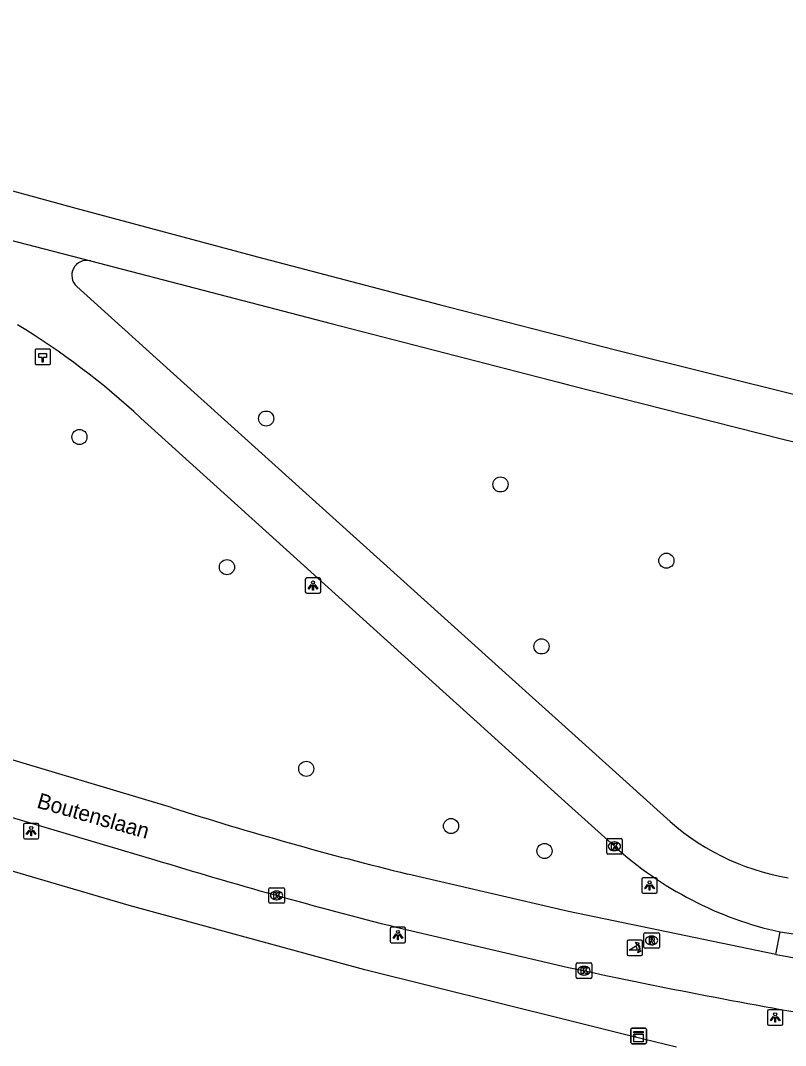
# Model space of a CAD drawing. Extents: x 160203 to 161526, y 379529 to 381797.
# Drawn here: x 160964.6 to 161014, y 381727.7 to 381793.9 of the extents above; entities that cross this region are included whole.
import ezdxf

# ---------------------------------------------------------------- set-up
doc = ezdxf.new("R2010")
doc.units = 0
for name, color, linetype in [('IMGEO_Boom', 7, 'Continuous'), ('IMGEO_Fietspad_gesloten', 7, 'Continuous'), ('IMGEO_Hectometerpaal', 7, 'Continuous'), ('IMGEO_Kast', 7, 'Continuous'), ('IMGEO_Kolk', 7, 'Continuous'), ('IMGEO_Lichtpunt', 7, 'Continuous'), ('IMGEO_Openbare_ruimte_label', 7, 'Continuous'), ('IMGEO_Poller', 7, 'Continuous'), ('IMGEO_Rijbaan_lokaal_gesloten', 7, 'Continuous'), ('IMGEO_Rijbaan_regionaal_gesloten', 7, 'Continuous'), ('IMGEO_Rioolput', 7, 'Continuous'), ('IMGEO_Verkeerseiland_open', 7, 'Continuous'), ('IMGEO_Voetpad_open', 7, 'Continuous')]:
    doc.layers.add(name, color=color, linetype=linetype)

msp = doc.modelspace()

# ---------------------------------------------------------------- linework, layer by layer
at = {"layer": 'IMGEO_Boom'}
for centre in [(160980.462, 381768.218), (160968.397, 381767.028), (160995.597, 381763.962), (161006.319, 381759.033), (160977.927, 381758.616), (160998.247, 381753.494), (160983.05, 381745.584), (160992.404, 381741.885), (160998.446, 381740.273)]:
    msp.add_circle(centre, 0.489, dxfattribs=at)
at = {"layer": 'IMGEO_Fietspad_gesloten'}
for points in [[(160974.354, 381743.083), (160951.205, 381750), (160921.356, 381758.919)], [(160913.952, 381757.333), (160917.435, 381756.293), (160921.939, 381754.948), (160938.727, 381750), (160941.676, 381749.131), (160960.405, 381743.51), (160973.259, 381739.709)], [(161013.385, 381733.585), (161000, 381736.362), (160989.623, 381738.784)], [(160988.869, 381735.348), (161000, 381732.75)]]:
    msp.add_lwpolyline(points, dxfattribs=at)
for centre, radius, start, end in [((161042.483, 381955.797), 223.358, 252.24042, 256.31036), ((161066.527, 382043.438), 317.727, 252.92958, 255.85265), ((161067.918, 382023.698), 295.194, 259.35423, 261.73648), ((161079.415, 382097.832), 373.62, 257.72776, 260.3637)]:
    msp.add_arc(centre, radius, start, end, dxfattribs=at)
at = {"layer": 'IMGEO_Hectometerpaal'}
for p, q in [((160966.449, 381772.71), (160965.608, 381772.71)), ((160966.449, 381772.71), (160965.608, 381772.71)), ((160966.533, 381771.794), (160966.533, 381772.635)), ((160966.533, 381771.794), (160966.533, 381772.635)), ((160965.533, 381772.626), (160965.533, 381771.785)), ((160965.533, 381772.626), (160965.533, 381771.785)), ((160965.617, 381771.71), (160966.458, 381771.71)), ((160965.617, 381771.71), (160966.458, 381771.71))]:
    msp.add_line(p, q, dxfattribs=at)
msp.add_lwpolyline([(160966.058, 381771.854), (160965.998, 381771.854), (160965.998, 381772.159), (160965.778, 381772.159), (160965.778, 381772.428), (160966.278, 381772.428), (160966.278, 381772.159), (160966.058, 381772.159), (160966.058, 381771.854)], dxfattribs=at)
for centre, start, end in [((160965.611, 381772.632), 92.4484, 184.28452), ((160965.611, 381772.632), 92.4484, 184.28452), ((160966.455, 381772.632), 2.4484, 94.28452), ((160966.455, 381772.632), 2.4484, 94.28452), ((160965.611, 381771.788), 182.4484, 274.28452), ((160965.611, 381771.788), 182.4484, 274.28452), ((160966.455, 381771.788), 272.4484, 4.28452), ((160966.455, 381771.788), 272.4484, 4.28452)]:
    msp.add_arc(centre, 0.0779, start, end, dxfattribs=at)
at = {"layer": 'IMGEO_Kast'}
for p, q in [((161004.026, 381727.893), (161004.026, 381728.734)), ((161004.026, 381728.734), (161004.026, 381727.893)), ((161004.101, 381728.818), (161004.942, 381728.818)), ((161004.942, 381728.818), (161004.101, 381728.818)), ((161005.026, 381728.743), (161005.026, 381727.902)), ((161005.026, 381727.902), (161005.026, 381728.743)), ((161004.951, 381727.818), (161004.11, 381727.818)), ((161004.11, 381727.818), (161004.951, 381727.818))]:
    msp.add_line(p, q, dxfattribs=at)
for points in [[(161004.221, 381728.608), (161004.821, 381728.608), (161004.821, 381728.523), (161004.221, 381728.523), (161004.221, 381728.608)], [(161004.221, 381728.433), (161004.821, 381728.433), (161004.821, 381727.944), (161004.221, 381727.944), (161004.221, 381728.433)]]:
    msp.add_lwpolyline(points, dxfattribs=at)
msp.add_circle((161004.305, 381728.282), 0.0377, dxfattribs=at)
for centre, start, end in [((161004.104, 381728.74), 92.4484, 184.28452), ((161004.104, 381728.74), 92.4484, 184.28452), ((161004.948, 381728.74), 2.4484, 94.28452), ((161004.948, 381728.74), 2.4484, 94.28452), ((161004.104, 381727.896), 182.4484, 274.28452), ((161004.104, 381727.896), 182.4484, 274.28452), ((161004.948, 381727.896), 272.4484, 4.28452), ((161004.948, 381727.896), 272.4484, 4.28452)]:
    msp.add_arc(centre, 0.0779, start, end, dxfattribs=at)
at = {"layer": 'IMGEO_Kolk'}
for p, q in [((161002.461, 381740.151), (161002.461, 381741.003)), ((161002.536, 381741.077), (161003.388, 381741.077)), ((161002.949, 381740.857), (161002.974, 381740.857)), ((161003.462, 381741.003), (161003.462, 381740.151)), ((161002.972, 381740.297), (161002.947, 381740.297)), ((161003.388, 381740.077), (161002.536, 381740.077)), ((160980.635, 381736.974), (160980.635, 381737.826)), ((160980.71, 381737.9), (160981.562, 381737.9)), ((160981.123, 381737.68), (160981.148, 381737.68)), ((160981.636, 381737.826), (160981.636, 381736.974)), ((160981.562, 381736.9), (160980.71, 381736.9)), ((160981.146, 381737.12), (160981.121, 381737.12)), ((161000.493, 381732.108), (161000.493, 381732.96)), ((161000.568, 381733.034), (161001.42, 381733.034)), ((161001.494, 381732.96), (161001.494, 381732.108)), ((161001.004, 381732.254), (161000.979, 381732.254)), ((161000.981, 381732.814), (161001.006, 381732.814)), ((161001.42, 381732.034), (161000.568, 381732.034))]:
    msp.add_line(p, q, dxfattribs=at)
for points in [[(161002.461, 381740.151), (161002.461, 381741.003)], [(161002.536, 381741.077), (161003.388, 381741.077)], [(161003.462, 381741.003), (161003.462, 381740.151)], [(161002.782, 381740.777), (161002.905, 381740.777), (161002.905, 381740.626), (161003.035, 381740.777), (161003.199, 381740.777), (161003.053, 381740.626), (161003.206, 381740.377), (161003.054, 381740.377), (161002.969, 381740.541), (161002.905, 381740.474), (161002.905, 381740.377), (161002.782, 381740.377), (161002.782, 381740.777)], [(161003.388, 381740.077), (161002.536, 381740.077)], [(160980.635, 381736.974), (160980.635, 381737.826)], [(160980.71, 381737.9), (160981.562, 381737.9)], [(160980.956, 381737.6), (160981.079, 381737.6), (160981.079, 381737.449), (160981.209, 381737.6), (160981.373, 381737.6), (160981.227, 381737.449), (160981.38, 381737.2), (160981.228, 381737.2), (160981.143, 381737.364), (160981.079, 381737.297), (160981.079, 381737.2), (160980.956, 381737.2), (160980.956, 381737.6)], [(160981.636, 381737.826), (160981.636, 381736.974)], [(160981.562, 381736.9), (160980.71, 381736.9)], [(161000.493, 381732.108), (161000.493, 381732.96)], [(161000.568, 381733.034), (161001.42, 381733.034)], [(161001.494, 381732.96), (161001.494, 381732.108)], [(161000.814, 381732.734), (161000.937, 381732.734), (161000.937, 381732.583), (161001.067, 381732.734), (161001.231, 381732.734), (161001.085, 381732.583), (161001.238, 381732.334), (161001.086, 381732.334), (161001.001, 381732.498), (161000.937, 381732.431), (161000.937, 381732.334), (161000.814, 381732.334), (161000.814, 381732.734)], [(161001.42, 381732.034), (161000.568, 381732.034)]]:
    msp.add_lwpolyline(points, dxfattribs=at)
for centre, start, end in [((161002.538, 381741.001), 91.55205, 178.44795), ((161002.538, 381741.001), 91.55205, 178.44795), ((161003.386, 381741.001), 1.55205, 88.44795), ((161003.386, 381741.001), 1.55205, 88.44795), ((161002.538, 381740.153), 181.55205, 268.44795), ((161002.538, 381740.153), 181.55205, 268.44795), ((161003.386, 381740.153), 271.55205, 358.44795), ((161003.386, 381740.153), 271.55205, 358.44795), ((160980.712, 381737.824), 91.55205, 178.44795), ((160980.712, 381737.824), 91.55205, 178.44795), ((160981.56, 381737.824), 1.55205, 88.44795), ((160981.56, 381737.824), 1.55205, 88.44795), ((160980.712, 381736.976), 181.55205, 268.44795), ((160980.712, 381736.976), 181.55205, 268.44795), ((160981.56, 381736.976), 271.55205, 358.44795), ((160981.56, 381736.976), 271.55205, 358.44795), ((161000.57, 381732.958), 91.55205, 178.44795), ((161000.57, 381732.958), 91.55205, 178.44795), ((161001.418, 381732.958), 1.55205, 88.44795), ((161001.418, 381732.958), 1.55205, 88.44795), ((161000.57, 381732.11), 181.55205, 268.44795), ((161000.57, 381732.11), 181.55205, 268.44795), ((161001.418, 381732.11), 271.55205, 358.44795), ((161001.418, 381732.11), 271.55205, 358.44795)]:
    msp.add_arc(centre, 0.0765, start, end, dxfattribs=at)
for centre, major_axis, ratio, start_param, end_param in [((161002.948, 381740.577), (-0.387, 0.002), 0.722429, 4.712389, 7.853982), ((161002.973, 381740.577), (-0.39, 0.002), 0.717154, 1.570796, 4.712389), ((160981.122, 381737.4), (-0.387, 0.002), 0.722429, 4.712389, 7.853982), ((160981.147, 381737.4), (-0.39, 0.002), 0.717154, 1.570796, 4.712389), ((161000.98, 381732.534), (-0.387, 0.002), 0.722429, 4.712389, 7.853982), ((161001.005, 381732.534), (-0.39, 0.002), 0.717154, 1.570796, 4.712389)]:
    msp.add_ellipse(centre, major_axis=major_axis, ratio=ratio, start_param=start_param, end_param=end_param, dxfattribs=at)
at = {"layer": 'IMGEO_Lichtpunt'}
for p, q in [((160982.987, 381757.826), (160982.987, 381757.019)), ((160982.987, 381757.826), (160982.987, 381757.019)), ((160983.889, 381757.921), (160983.081, 381757.921)), ((160983.889, 381757.921), (160983.081, 381757.921)), ((160983.983, 381757.019), (160983.983, 381757.826)), ((160983.983, 381757.019), (160983.983, 381757.826)), ((160983.081, 381756.925), (160983.889, 381756.925)), ((160983.081, 381756.925), (160983.889, 381756.925)), ((160964.778, 381741.963), (160964.778, 381741.156)), ((160964.778, 381741.963), (160964.778, 381741.156)), ((160965.68, 381742.058), (160964.872, 381742.058)), ((160965.68, 381742.058), (160964.872, 381742.058)), ((160965.774, 381741.156), (160965.774, 381741.963)), ((160965.774, 381741.156), (160965.774, 381741.963)), ((160964.872, 381741.062), (160965.68, 381741.062)), ((160964.872, 381741.062), (160965.68, 381741.062)), ((161004.731, 381738.445), (161004.731, 381737.638)), ((161004.731, 381738.445), (161004.731, 381737.638)), ((161005.633, 381738.54), (161004.825, 381738.54)), ((161005.633, 381738.54), (161004.825, 381738.54)), ((161005.727, 381737.638), (161005.727, 381738.445)), ((161005.727, 381737.638), (161005.727, 381738.445)), ((161004.825, 381737.544), (161005.633, 381737.544)), ((161004.825, 381737.544), (161005.633, 381737.544)), ((160988.471, 381735.245), (160988.471, 381734.438)), ((160988.471, 381735.245), (160988.471, 381734.438)), ((160989.373, 381735.34), (160988.565, 381735.34)), ((160989.373, 381735.34), (160988.565, 381735.34)), ((160989.467, 381734.438), (160989.467, 381735.245)), ((160989.467, 381734.438), (160989.467, 381735.245)), ((160988.565, 381734.344), (160989.373, 381734.344)), ((160988.565, 381734.344), (160989.373, 381734.344)), ((161012.847, 381729.918), (161012.847, 381729.111)), ((161012.847, 381729.918), (161012.847, 381729.111)), ((161013.749, 381730.013), (161012.941, 381730.013)), ((161013.749, 381730.013), (161012.941, 381730.013)), ((161013.843, 381729.111), (161013.843, 381729.918)), ((161013.843, 381729.111), (161013.843, 381729.918)), ((161012.941, 381729.017), (161013.749, 381729.017)), ((161012.941, 381729.017), (161013.749, 381729.017))]:
    msp.add_line(p, q, dxfattribs=at)
for points in [[(160983.361, 381757.49), (160983.4, 381757.462), (160983.212, 381757.2), (160983.174, 381757.227), (160983.361, 381757.49)], [(160983.463, 381757.442), (160983.51, 381757.442), (160983.51, 381757.12), (160983.463, 381757.12), (160983.463, 381757.442)], [(160983.573, 381757.462), (160983.611, 381757.489), (160983.798, 381757.227), (160983.759, 381757.199), (160983.573, 381757.462)], [(160965.152, 381741.627), (160965.191, 381741.599), (160965.003, 381741.337), (160964.965, 381741.364), (160965.152, 381741.627)], [(160965.254, 381741.579), (160965.301, 381741.579), (160965.301, 381741.257), (160965.254, 381741.257), (160965.254, 381741.579)], [(160965.364, 381741.599), (160965.402, 381741.626), (160965.589, 381741.364), (160965.55, 381741.336), (160965.364, 381741.599)], [(161005.105, 381738.109), (161005.144, 381738.081), (161004.956, 381737.819), (161004.918, 381737.846), (161005.105, 381738.109)], [(161005.207, 381738.061), (161005.254, 381738.061), (161005.254, 381737.739), (161005.207, 381737.739), (161005.207, 381738.061)], [(161005.317, 381738.081), (161005.355, 381738.108), (161005.542, 381737.846), (161005.503, 381737.818), (161005.317, 381738.081)], [(160988.845, 381734.909), (160988.884, 381734.881), (160988.696, 381734.619), (160988.658, 381734.646), (160988.845, 381734.909)], [(160989.057, 381734.881), (160989.095, 381734.908), (160989.282, 381734.646), (160989.243, 381734.618), (160989.057, 381734.881)], [(160988.947, 381734.861), (160988.994, 381734.861), (160988.994, 381734.539), (160988.947, 381734.539), (160988.947, 381734.861)], [(161013.221, 381729.582), (161013.26, 381729.554), (161013.072, 381729.292), (161013.034, 381729.319), (161013.221, 381729.582)], [(161013.433, 381729.554), (161013.471, 381729.581), (161013.658, 381729.319), (161013.619, 381729.291), (161013.433, 381729.554)], [(161013.323, 381729.534), (161013.37, 381729.534), (161013.37, 381729.212), (161013.323, 381729.212), (161013.323, 381729.534)]]:
    msp.add_lwpolyline(points, dxfattribs=at)
for centre in [(160983.486, 381757.624), (160965.277, 381741.761), (161005.23, 381738.243), (160988.97, 381735.043), (161013.346, 381729.716)]:
    msp.add_circle(centre, 0.0994, dxfattribs=at)
for centre, start, end in [((160983.081, 381757.826), 90, 180), ((160983.081, 381757.826), 90, 180), ((160983.889, 381757.826), 0, 90), ((160983.889, 381757.826), 0, 90), ((160983.081, 381757.019), 180, 270), ((160983.081, 381757.019), 180, 270), ((160983.889, 381757.019), 270, 0), ((160983.889, 381757.019), 270, 360), ((160964.872, 381741.963), 90, 180), ((160964.872, 381741.963), 90, 180), ((160965.68, 381741.963), 0, 90), ((160965.68, 381741.963), 0, 90), ((160964.872, 381741.156), 180, 270), ((160964.872, 381741.156), 180, 270), ((160965.68, 381741.156), 270, 0), ((160965.68, 381741.156), 270, 360), ((161004.825, 381738.445), 90, 180), ((161004.825, 381738.445), 90, 180), ((161005.633, 381738.445), 0, 90), ((161005.633, 381738.445), 0, 90), ((161004.825, 381737.638), 180, 270), ((161004.825, 381737.638), 180, 270), ((161005.633, 381737.638), 270, 0), ((161005.633, 381737.638), 270, 360), ((160988.565, 381735.245), 90, 180), ((160988.565, 381735.245), 90, 180), ((160989.373, 381735.245), 0, 90), ((160989.373, 381735.245), 0, 90), ((160988.565, 381734.438), 180, 270), ((160988.565, 381734.438), 180, 270), ((160989.373, 381734.438), 270, 0), ((160989.373, 381734.438), 270, 360), ((161012.941, 381729.918), 90, 180), ((161012.941, 381729.918), 90, 180), ((161013.749, 381729.918), 0, 90), ((161013.749, 381729.918), 0, 90), ((161012.941, 381729.111), 180, 270), ((161012.941, 381729.111), 180, 270), ((161013.749, 381729.111), 270, 0), ((161013.749, 381729.111), 270, 360)]:
    msp.add_arc(centre, 0.0946, start, end, dxfattribs=at)
at = {"layer": 'IMGEO_Poller'}
for p, q in [((161003.784, 381734.421), (161003.784, 381733.614)), ((161003.784, 381734.421), (161003.784, 381733.614)), ((161004.686, 381734.516), (161003.878, 381734.516)), ((161004.686, 381734.516), (161003.878, 381734.516)), ((161004.78, 381733.614), (161004.78, 381734.421)), ((161004.78, 381733.614), (161004.78, 381734.421)), ((161003.878, 381733.519), (161004.686, 381733.519)), ((161003.878, 381733.519), (161004.686, 381733.519))]:
    msp.add_line(p, q, dxfattribs=at)
for points in [[(161004.463, 381734.245), (161004.451, 381734.172), (161004.326, 381734.377)], [(161004.326, 381734.377), (161004.557, 381734.311), (161004.486, 381734.279)], [(161004.419, 381733.872), (161003.906, 381733.872), (161004.336, 381734.147)], [(161004.479, 381733.7), (161004.545, 381733.931), (161004.575, 381733.863)], [(161004.611, 381733.836), (161004.683, 381733.825), (161004.479, 381733.7)]]:
    msp.add_lwpolyline(points, dxfattribs=at)
for centre, radius, start, end in [((161003.878, 381734.421), 0.0946, 90, 180), ((161003.878, 381734.421), 0.0946, 90, 180), ((161004.105, 381733.932), 0.476, 351.75274, 41.16905), ((161004.105, 381733.932), 0.516, 349.35686, 42.29123), ((161004.686, 381734.421), 0.0946, 0, 90), ((161004.686, 381734.421), 0.0946, 0, 90), ((161003.878, 381733.614), 0.0946, 180, 270), ((161003.878, 381733.614), 0.0946, 180, 270), ((161004.091, 381733.922), 0.332, 351.32473, 42.4854), ((161004.686, 381733.614), 0.0946, 270, 0), ((161004.686, 381733.614), 0.0946, 270, 0)]:
    msp.add_arc(centre, radius, start, end, dxfattribs=at)
at = {"layer": 'IMGEO_Rijbaan_lokaal_gesloten'}
for points in [[(161006.131, 381742.564), (161000, 381748.093), (160998.079, 381749.825), (160997.885, 381750), (160974.918, 381770.704), (160968.226, 381776.744)], [(161002.963, 381740.577), (161000, 381743.257), (160992.734, 381749.829), (160992.545, 381750), (160972.366, 381768.251)], [(161013.669, 381735.04), (161017.649, 381734.443), (161023.174, 381733.608)]]:
    msp.add_lwpolyline(points, dxfattribs=at)
for centre, radius, start, end in [((160968.881, 381777.467), 0.976, 76.72075, 227.84407), ((160938.312, 381731.524), 50.085, 47.16202, 58.60476), ((161016.769, 381753.797), 15.471, 226.55789, 260.36896), ((161018.776, 381758.033), 23.554, 227.82783, 257.47737)]:
    msp.add_arc(centre, radius, start, end, dxfattribs=at)
at = {"layer": 'IMGEO_Rijbaan_regionaal_gesloten'}
for points in [[(160924.859, 381793.944), (160925.219, 381793.836), (160932.99, 381791.589), (160940.822, 381789.378), (160948.647, 381787.174), (160956.184, 381785.094), (160968.166, 381781.822), (160979.903, 381778.661), (160991.646, 381775.583), (161003.024, 381772.663), (161015.054, 381769.67), (161027.088, 381766.724), (161038.576, 381764.048), (161050.554, 381761.325), (161062.699, 381758.567), (161077.95, 381755.315)], [(160962.525, 381780.117), (160969.105, 381778.417)], [(160969.105, 381778.417), (160984.653, 381774.366), (160999.35, 381770.568), (161000, 381770.403), (161013.924, 381766.869), (161028.59, 381763.382), (161044.221, 381759.753), (161054.991, 381757.276), (161068.719, 381754.268), (161077.399, 381752.406)]]:
    msp.add_lwpolyline(points, dxfattribs=at)
at = {"layer": 'IMGEO_Rioolput'}
for p, q in [((161004.861, 381734.062), (161004.861, 381734.914)), ((161004.936, 381734.988), (161005.788, 381734.988)), ((161005.862, 381734.914), (161005.862, 381734.062)), ((161005.372, 381734.208), (161005.347, 381734.208)), ((161005.349, 381734.768), (161005.374, 381734.768)), ((161005.788, 381733.988), (161004.936, 381733.988))]:
    msp.add_line(p, q, dxfattribs=at)
for points in [[(161004.861, 381734.062), (161004.861, 381734.914)], [(161004.936, 381734.988), (161005.788, 381734.988)], [(161005.862, 381734.914), (161005.862, 381734.062)], [(161005.45, 381734.686), (161005.198, 381734.688), (161005.198, 381734.288)], [(161005.198, 381734.288), (161005.322, 381734.288), (161005.322, 381734.45), (161005.333, 381734.45)], [(161005.376, 381734.607), (161005.322, 381734.607), (161005.322, 381734.526)], [(161005.322, 381734.526), (161005.374, 381734.526)], [(161005.38, 381734.421), (161005.451, 381734.288), (161005.591, 381734.288), (161005.526, 381734.414)], [(161005.788, 381733.988), (161004.936, 381733.988)]]:
    msp.add_lwpolyline(points, dxfattribs=at)
for centre, radius, start, end in [((161004.938, 381734.912), 0.0765, 91.55205, 178.44795), ((161004.938, 381734.912), 0.0765, 91.55205, 178.44795), ((161005.786, 381734.912), 0.0765, 1.55205, 88.44795), ((161005.786, 381734.912), 0.0765, 1.55205, 88.44795), ((161005.332, 381734.397), 0.0533, 26.02933, 88.69889), ((161005.358, 381734.715), 0.19, 274.7715, 282.96867), ((161005.382, 381734.511), 0.0964, 77.00612, 93.18647), ((161005.396, 381734.568), 0.0378, 276.66336, 79.67722), ((161005.449, 381734.576), 0.109, 350.36119, 89.41601), ((161005.447, 381734.576), 0.112, 277.58423, 350.98172), ((161005.431, 381734.361), 0.108, 29.51342, 73.79051), ((161004.938, 381734.064), 0.0765, 181.55205, 268.44795), ((161004.938, 381734.064), 0.0765, 181.55205, 268.44795), ((161005.786, 381734.064), 0.0765, 271.55205, 358.44795), ((161005.786, 381734.064), 0.0765, 271.55205, 358.44795)]:
    msp.add_arc(centre, radius, start, end, dxfattribs=at)
for centre, major_axis, ratio, start_param, end_param in [((161005.348, 381734.488), (-0.387, 0.002), 0.722429, 4.712389, 7.853982), ((161005.373, 381734.488), (-0.39, 0.002), 0.717154, 1.570796, 4.712389)]:
    msp.add_ellipse(centre, major_axis=major_axis, ratio=ratio, start_param=start_param, end_param=end_param, dxfattribs=at)
at = {"layer": 'IMGEO_Verkeerseiland_open'}
msp.add_lwpolyline([(161013.385, 381733.585), (161013.669, 381735.04)], dxfattribs=at)
at = {"layer": 'IMGEO_Voetpad_open'}
msp.add_lwpolyline([(161006.975, 381727.585), (161004.832, 381728.107), (161003.097, 381728.539), (161000, 381729.31), (160986.832, 381732.59), (160971.619, 381736.753), (160928.455, 381749.417)], dxfattribs=at)

# ---------------------------------------------------------------- texts
at = {"layer": 'IMGEO_Openbare_ruimte_label'}
msp.add_text('Boutenslaan', height=1, rotation=344.10181, dxfattribs=at).set_placement((160965.589, 381743.084))

doc.saveas('drawing.dxf')
